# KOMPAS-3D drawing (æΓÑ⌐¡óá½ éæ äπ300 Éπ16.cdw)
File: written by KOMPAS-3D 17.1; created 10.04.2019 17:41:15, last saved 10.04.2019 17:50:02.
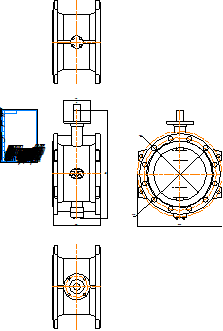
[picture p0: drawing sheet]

Sheet 1: A4, portrait

Title block, sheet 1: name: Стейнвал ВС Ду300 Ру16; material: Внимание! Данный продукт является объектом авторского права ООО «Торговый Дом АДЛ». / Запрещается изменение, копирование, распространение / (в том числе путем копирования на другие сайты и ресурсы в Интернете) / или любое иное использование информации и объектов без предварительного / согласия правообладателя (ООО «Торговый Дом АДЛ»).; mass: 84,82; sheets: 1; organisation: ООО "Торговый дом АДЛ"; sheet format: A4; stored path: \\adlc.lan\data\АДЛ_ПКД\3D-модели\ADL production\Дисковые поворотные затворы СТЕЙНВАЛ\Двухэксцентриковый ВС\KOMPAS 2D\Стейнвал ВС Ду300 Ру16.cdw

Views: Вид 1, Проекционный вид 2, Проекционный вид 3, Проекционный вид 4
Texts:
  user
Dimensions and other numbers on the sheet: 262; 40; 150; 614; 410; 482,74; 300; 1:1; 1; 84,82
